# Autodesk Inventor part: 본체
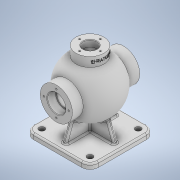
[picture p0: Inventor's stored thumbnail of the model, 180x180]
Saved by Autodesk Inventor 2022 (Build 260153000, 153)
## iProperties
Created: 2024-04
Part Number: 본체
Material: 일반
Document SubType Name: Modeling
Designer: Admin
Density: 1 g/cm^3
Appearance: 기본값
Author: Admin
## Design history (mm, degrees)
sketch "스케치1"
  geometry: L1 (-54, 0)-(54, 0); A1 r 54 centre (0, 0) between (-54, 0) and (54, 0); 1 further point
  constraints: 2 end point, 2 point on circle, 1 centre point, 1 coincident, 1 horizontal, 1 midpoint
  dimensions: "d0" = 108 diameter of A1
revolve "회전1" sketch "스케치1" stored, may be unused: angle "d1" = 90 deg
node "작업 평면1"
sketch "스케치2"
  geometry: C1 r 31 at (0, 0); 1 further point
  constraints: 1 centre point, 1 coincident
  dimensions: "d3" = 62 diameter of C1
extrude "돌출1" join sketch "스케치2" distance "d4" = 130; taper "d5" = 0 deg
node "작업 평면2"
sketch "스케치3"
  geometry: L1 (62.5, -62.5)-(-62.5, -62.5); L2 (-62.5, -62.5)-(-62.5, 62.5); L3 (-62.5, 62.5)-(62.5, 62.5); L4 (62.5, 62.5)-(62.5, -62.5); L5 (62.5, -62.5)-(-62.5, 62.5); L6 (-62.5, -62.5)-(62.5, 62.5); 1 further point
  constraints: 12 end point, 2 midpoint, 2 parallel, 1 horizontal, 1 perpendicular
  dimensions: "d7" = 125 distance of L2.end L3.end; "d8" = 125 distance of L1.end L2.end
extrude "돌출2" join sketch "스케치3" distance "d9" = 10; taper "d10" = 0 deg
sketch "스케치4"
  geometry: L1 (62.5, -75)-(-62.5, -75) reference; L2 (-50.5, -75)-(-23.202, 0); L3 (-23.202, 0)-(23.202, 0); L4 (23.202, 0)-(50.5, -75); L5 (-62.5, -85)-(-62.5, -75) reference; L6 (62.5, -85)-(62.5, -75) reference; 1 further point
  constraints: 6 end point, 2 point on line, 1 midpoint, 1 parallel
  dimensions: "d11" = 12 distance from line of L5 L2.start; "d12" = 12 distance of L1.start L4.end; "d13" = 20 deg angle of L5 L2; "d14" = 20 deg angle of L6 L4
extrude "돌출3" join sketch "스케치4" stored distance "d15" = 8; taper "d16" = 0 deg
sketch "스케치5"
  geometry: L1 (-75, -62.5)-(-75, 62.5) reference; L2 (-75, 50.5)-(0, 23.202); L3 (0, 23.202)-(0, -23.202); L4 (0, -23.202)-(-75, -50.5); L5 (-75, 50.5)-(-75, -50.5); L6 (-85, 62.5)-(-75, 62.5) reference; L7 (-85, -62.5)-(-75, -62.5) reference; 1 further point
  constraints: 8 end point, 2 point on line, 1 collinear, 1 midpoint, 1 parallel
  dimensions: "d17" = 12 distance from line of L6 L2.start; "d18" = 12 distance from line of L4.end L7; "d19" = 20 deg angle of L6 L2; "d20" = 20 deg angle of L7 L4
extrude "돌출4" join sketch "스케치5" stored distance "d21" = 8; taper "d22" = 0 deg
node "작업 평면3"
sketch "스케치6"
  geometry: C1 r 27 at (0, 0); 1 further point
  constraints: 1 centre point, 1 coincident
  dimensions: "d24" = 54 diameter of C1
extrude "돌출5" join sketch "스케치6" stored distance "d25" = 8; taper "d26" = 0 deg
fillet "모깎기1" dims "d27" = 16
sketch "스케치7"
  geometry: L1 (46.5, 62.5)-(-46.5, 62.5) reference; L2 (62.5, -46.5)-(62.5, 46.5) reference; L3 (-46.5, -62.5)-(46.5, -62.5) reference; L4 (-62.5, 46.5)-(-62.5, -46.5) reference; C1 r 5.5 at (-46.5, -46.5); C2 r 5.5 at (-46.5, 46.5); C3 r 5.5 at (46.5, 46.5); C4 r 5.5 at (46.5, -46.5); A1 r 16 centre (-46.5, 46.5) between (-46.5, 62.5) and (-62.5, 46.5) reference; A2 r 16 centre (46.5, 46.5) between (62.5, 46.5) and (46.5, 62.5) reference; A3 r 16 centre (46.5, -46.5) between (46.5, -62.5) and (62.5, -46.5) reference; A4 r 16 centre (-46.5, -46.5) between (-62.5, -46.5) and (-46.5, -62.5) reference; 1 further point
  constraints: 4 centre point, 4 coincident
  dimensions: "d28" = 11 diameter of C1; "d29" = 11 diameter of C2; "d30" = 11 diameter of C3; "d31" = 11 diameter of C4
extrude "돌출6" cut sketch "스케치7" extent not by distance; stored distance "d32" = 0; taper "d33" = 0 deg
sketch "스케치8"
  geometry: L1 (31, 65)-(-31, 65) reference; L2 (0, 65)-(17.5, 65); L3 (17.5, 65)-(17.5, 49); L4 (17.5, 49)-(0, 49); L5 (0, 49)-(0, 65); L6 (0, 49)-(15, 49); L7 (15, 49)-(15, 41.364); L8 (0, 40.506)-(0, 49); L9 (-31, -65)-(31, -65) reference; L10 (0, -65)-(17.5, -65); L11 (17.5, -65)-(17.5, -49); L12 (17.5, -49)-(0, -49); L13 (0, -49)-(0, -65); L14 (0, -49)-(15, -49); L15 (15, -49)-(15, -41.364); L16 (0, -40.258)-(0, -49); L17 (0, 100.767)-(0, -143.291); A1 r 44 centre (0, 0) between (15, 41.364) and (15, -41.364); 7 further points
  constraints: 30 end point, 6 parallel, 4 horizontal, 4 perpendicular, 3 point on line, 2 midpoint, 2 point on circle, 1 centre point, 1 coincident, 1 vertical
  dimensions: "d34" = 88 diameter of A1; "d35" = 16 distance between parallel lines of L1 L4; "d36" = 16 distance between parallel lines of L10 L12; "d37" = 35 diameter of L3 L17; "d38" = 30 diameter of L7 L17
revolve "회전2" sketch "스케치8" stored, may be unused: angle "d39" = 90 deg
sketch "스케치9"
  geometry: 2 further points
  constraints: 1 vertical alignment
  dimensions: "d40" = 24 distance of point (0, 0) point (0, 24)
hole "구멍1" sketch "스케치9" at (0, 24) diameter "d41" = 3.242; stored, may be unused: countersink angle "d45" = 90 deg, drill point angle "d47" = 118 deg; dims "d42" = 12, "d43" = 4, "d44" = 2, "d46" = 15
sketch "스케치10"
  geometry: C1 r 13 at (0, 0); 1 further point
  constraints: 1 centre point, 1 coincident
  dimensions: "d51" = 26 diameter of C1
extrude "돌출7" cut sketch "스케치10" stored distance "d52" = 10; taper "d53" = 0 deg
fillet "모깎기2" dims "d54" = 3
fillet "모깎기3" dims "d55" = 3
fillet "모깎기4" dims "d56" = 3
fillet "모깎기5" dims "d57" = 3
chamfer "모따기1" distance "d58" = 1; stored, may be unused: second distance "d59" = 2, angle "d60" = 45 deg
chamfer "모따기2" distance "d61" = 1; stored, may be unused: second distance "d62" = 2, angle "d63" = 45 deg
chamfer "모따기3" distance "d64" = 1; stored, may be unused: second distance "d65" = 2, angle "d66" = 45 deg
node "작업 평면4"
sketch "스케치11"
  geometry: L1 (65, -27)-(65, 27) reference; 2 further points
  constraints: 1 horizontal alignment, 1 other
  dimensions: "d68" = 9 distance from line of point (56, 0) L1
feature "엠보싱1" sketch "스케치11" dims "d69" = 0.5, "d70" = 0
sketch "스케치12"
  geometry: 2 further points
  constraints: 1 vertical alignment
  dimensions: "d71" = 20 distance of point (0, 0) point (0, 20)
hole "구멍2" sketch "스케치12" at (0, 20) diameter "d72" = 3.242; stored, may be unused: countersink angle "d76" = 90 deg, drill point angle "d78" = 118 deg; dims "d73" = 9, "d74" = 4, "d75" = 2, "d77" = 11
node "솔리드1"
pattern_circular "원형 패턴1" dims angle "d49" = 360 deg
mirror "미러1"
pattern_circular "원형 패턴2" dims angle "d80" = 360 deg
node "투영된 루프1"
feature "A9D066F2-1C7D-4E18-AEED-F7BC21143FA4" dims "d41" = 3.242, "d42" = 12, "d43" = 4, "d44" = 2, "d45" = 90 deg, "d46" = 15, "d47" = 118 deg
other parameters: "d2" = 65, "d6" = -85, "d23" = 65, "d67" = 27
